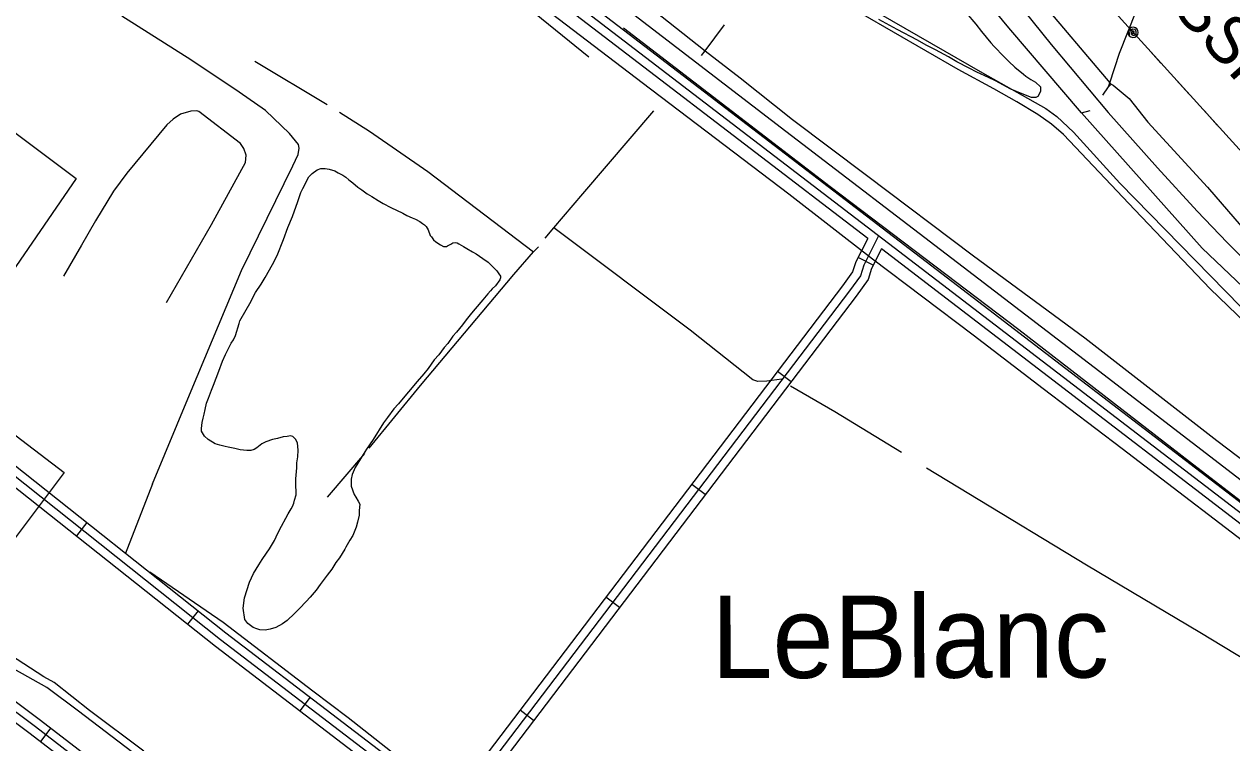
# Model space of a CAD drawing. Extents: x 3324104 to 3361979, y 612876 to 638273.
# Drawn here: x 3355626 to 3357754, y 632230 to 633497 of the extents above; entities that cross this region are included whole.
import ezdxf

# ---------------------------------------------------------------- set-up
doc = ezdxf.new("R2010")
doc.units = 0
for name, color, linetype in [('V-RAIL-IDEN', 7, 'Continuous'), ('V-RAIL-TRAK', 7, 'Continuous'), ('V-ROAD-CNTR', 7, 'Continuous'), ('V-SITE-OTLN', 7, 'Continuous'), ('V-SITE-VEGE', 7, 'Continuous'), ('V-TOPO-GNAM-IDEN', 7, 'Continuous'), ('V-TOPO-SHOR', 7, 'Continuous'), ('V-UTIL-LINE', 7, 'Continuous')]:
    doc.layers.add(name, color=color, linetype=linetype)

msp = doc.modelspace()

# ---------------------------------------------------------------- linework, layer by layer
at = {"layer": 'V-RAIL-TRAK'}
msp.add_line((3355679, 632336.4), (3355660.4, 632346.6), dxfattribs=at)
for points in [[(3356215.6, 635761.2), (3356284.7, 635591.1), (3356397, 635315.7), (3356492.2, 635083.5), (3356560, 634919.7), (3356618.9, 634783), (3356687.5, 634633.1), (3356729.4, 634548), (3356813.2, 634386.8), (3356880.5, 634264.7), (3356940.4, 634162), (3356992, 634077.6), (3357074.6, 633949.1), (3357125.6, 633873), (3357175.2, 633801), (3357225.5, 633732.6), (3357325.5, 633598.4), (3357435.2, 633461.4), (3357535.9, 633341.2), (3357622.9, 633243.9), (3357692.7, 633167.7), (3357745.2, 633112.4), (3357828.1, 633029.8)], [(3355803.7, 634092.1), (3356006.4, 633937.2), (3356202.2, 633787.1), (3356331, 633688.9), (3356519.9, 633543.8), (3356715, 633394.4), (3356973.1, 633198), (3357120.5, 633083.7)], [(3355660.4, 632346.6), (3355497.5, 632452.3), (3355389.9, 632538.5), (3355338.1, 632579), (3355081.1, 632775.2), (3354838.1, 632959.9), (3354736.5, 633039.5), (3354665.7, 633092.7)], [(3357120.5, 633083.7), (3357298, 632949.6), (3357421.2, 632854.9), (3357560.3, 632749), (3357832.3, 632540.7), (3358017.7, 632399.1), (3358165.1, 632285.5)], [(3356244.8, 631902.7), (3356234.1, 631908.9), (3356189.6, 631934.7), (3356156, 631953.1), (3356118.6, 631981.2), (3356060.8, 632025.8), (3355972.7, 632092.7), (3355862.4, 632178.6), (3355721.6, 632286), (3355665.9, 632327.4), (3355608.6, 632360), (3355536.8, 632401.4), (3355482, 632434.7), (3355447.1, 632458)], [(3355836.9, 632215.1), (3355741.3, 632287), (3355679, 632336.4)]]:
    msp.add_lwpolyline(points, dxfattribs=at)
at = {"layer": 'V-ROAD-CNTR'}
for p, q in [((3357122, 633072.4), (3357095.3, 633086)), ((3356977.2, 632866.7), (3356953.3, 632884.8)), ((3356826, 632667.6), (3356802.1, 632685.7)), ((3355736.7, 632618.4), (3355718.1, 632594.9)), ((3356674.8, 632468.5), (3356650.9, 632486.6)), ((3355932.5, 632463), (3355913.9, 632439.5)), ((3356130.1, 632310.3), (3356111.9, 632286.4)), ((3356523.6, 632269.4), (3356499.8, 632287.5)), ((3355673, 632256.3), (3355654.7, 632232.5))]:
    msp.add_line(p, q, dxfattribs=at)
for points in [[(3358019.6, 632437.2), (3357976, 632476), (3357233.8, 633045.3), (3356292.3, 633766.7), (3355060.3, 634700.7), (3354190.2, 635372.4), (3353533, 635873.8), (3353385.4, 635986.9)], [(3357973.3, 632497), (3357242.9, 633057.2), (3356301.4, 633778.6), (3355809.2, 634151.8)], [(3357112.4, 633119.4), (3356283.2, 633754.7), (3355799.1, 634121.8)], [(3356667, 633540.2), (3356968.1, 633308.6), (3357270.4, 633077.1), (3357511.3, 632892.6), (3357769.9, 632693)], [(3354440.4, 633195.5), (3354595.2, 633073.3), (3354743.7, 632957.5), (3354931.2, 632814.7), (3355122, 632677.9), (3355384.5, 632472.3), (3355654.9, 632270.2), (3355853.8, 632116.7), (3356020.3, 631989.3), (3356157.5, 631898.2), (3356178.3, 631895.5), (3356203.4, 631905.3), (3356249.5, 631948.5), (3356354.1, 632101)], [(3354421.8, 633171.9), (3354576.7, 633049.7), (3354725.4, 632933.7), (3354913.4, 632790.6), (3355104, 632653.9), (3355366.2, 632448.4), (3355636.8, 632246.3), (3355835.5, 632092.9), (3356002.9, 631964.8), (3356146.7, 631869.4), (3356182.1, 631864.8), (3356219.7, 631879.4), (3356272.4, 631928.8), (3356377.9, 632082.7)], [(3356374.5, 632104.3), (3356260.9, 631938.6), (3356211.5, 631892.3), (3356180.2, 631880.2), (3356152.1, 631883.8), (3356011.6, 631977.1), (3355844.7, 632104.8), (3355645.9, 632258.3), (3355375.4, 632460.4), (3355113, 632665.9), (3354922.3, 632802.6), (3354734.5, 632945.6), (3354586, 633061.5), (3354431.1, 633183.7)], [(3357131.4, 633123.7), (3357105.2, 633072.4), (3357099.2, 633053.5), (3357079.8, 633026.7), (3356384.2, 632110.6)], [(3357112.4, 633119.4), (3357091.3, 633078.1), (3357085.6, 633060.4), (3357067.8, 633035.6), (3356374.8, 632122.9)], [(3357136.6, 633100.9), (3357119.1, 633066.6), (3357112.7, 633046.7), (3357091.9, 633017.8), (3356398.6, 632104.7)], [(3358009.6, 632426), (3357966.4, 632464.5), (3357224.6, 633033.4), (3357136.6, 633100.9)], [(3355577.8, 633036.6), (3355588.3, 633022), (3355593.1, 633012.6), (3355592.9, 632993.3), (3355581.9, 632970.1), (3355539.7, 632906.8), (3355517.9, 632876.8), (3355513.2, 632836.4), (3355520.2, 632806.1), (3355531.4, 632780.9), (3355544.4, 632758.3), (3355575.1, 632727.6), (3355972.1, 632412.3), (3356882.6, 631715.2), (3357344.5, 631367.3), (3357364.6, 631354.1), (3357376.9, 631347.5), (3357393.1, 631340.4), (3357408.3, 631337.4), (3357420.1, 631337.3), (3357629.2, 631337.4), (3357692.6, 631341.9), (3357746, 631347.5), (3357788, 631350.2)], [(3355590, 633045.4), (3355601.2, 633029.8), (3355608.2, 633016.1), (3355607.9, 632989.9), (3355595, 632962.7), (3355552, 632898.2), (3355532.3, 632871.2), (3355528.4, 632837.2), (3355534.5, 632810.8), (3355544.7, 632787.8), (3355556.4, 632767.5), (3355585.1, 632738.8), (3355981.3, 632424.2), (3356374.8, 632122.9)], [(3355565.6, 633027.9), (3355575.5, 633014.2), (3355578.1, 633009), (3355577.9, 632996.8), (3355568.8, 632977.5), (3355527.3, 632915.3), (3355503.4, 632882.4), (3355498, 632835.6), (3355505.9, 632801.3), (3355518, 632774.1), (3355532.4, 632749.1), (3355565.1, 632716.3), (3355962.9, 632400.5), (3356354.1, 632101)]]:
    msp.add_lwpolyline(points, dxfattribs=at)
at = {"layer": 'V-SITE-OTLN'}
for points in [[(3355383.1, 633476), (3355717.7, 633225.3), (3355590.8, 633040)], [(3355524.4, 632837.6), (3355696.7, 632706.6), (3355535.7, 632492.5)]]:
    msp.add_lwpolyline(points, dxfattribs=at)
at = {"layer": 'V-SITE-VEGE'}
for points in [[(3357285.6, 633517.2), (3357302.6, 633497), (3357312.8, 633484.5), (3357329.2, 633464.2), (3357334.9, 633458), (3357351.8, 633440.3), (3357360.6, 633431.5), (3357371.4, 633421.1), (3357386.8, 633409.1), (3357390.9, 633405.4), (3357399.7, 633399.7), (3357407.9, 633395), (3357416.6, 633386.6), (3357416.6, 633378.4), (3357411.9, 633369.6), (3357408.2, 633367.6), (3357401, 633368.1), (3357387.1, 633372.9), (3357374.2, 633378.6), (3357364.4, 633382.8), (3357337.6, 633397), (3357325.2, 633403.3), (3357304.6, 633412.7), (3357291.2, 633419.5), (3357269.1, 633431), (3357254.6, 633439.4), (3357231.5, 633451.9), (3357215, 633460.3), (3357200, 633469.2), (3357164, 633488), (3357131.5, 633505.3)], [(3356005.8, 632974.3), (3356025.7, 633008.9), (3356029.3, 633016.6), (3356033.5, 633024.3), (3356043.4, 633038.7), (3356050.7, 633050.6), (3356063.3, 633073.2), (3356071.7, 633089.2), (3356083.2, 633117.6), (3356090.6, 633138.7), (3356098.5, 633157.8), (3356108, 633184.6), (3356113.7, 633200.6), (3356116.9, 633207.3), (3356127.4, 633227.9), (3356133.6, 633234.1), (3356142.4, 633240.2), (3356148.6, 633242.8), (3356156.4, 633242.7), (3356163.6, 633241.6), (3356173.4, 633238.5), (3356179.1, 633235.3), (3356187.3, 633231.1), (3356192.5, 633227.5), (3356198.1, 633222.8), (3356204.8, 633217.6), (3356214.1, 633209.8), (3356220.8, 633205.1), (3356230.6, 633197.8), (3356238.3, 633193.6), (3356249.6, 633186.3), (3356258.4, 633181.1), (3356272.3, 633173.7), (3356292.9, 633163.8), (3356300.1, 633160.1), (3356309.4, 633155.9), (3356315.6, 633153.3), (3356323.3, 633149.1), (3356327.9, 633146), (3356331.5, 633143.4), (3356334.1, 633140.3), (3356337.7, 633134.6), (3356341.2, 633124.7), (3356343.8, 633122.1), (3356347.4, 633116.9), (3356351.5, 633113.3), (3356359.7, 633108), (3356364.9, 633105.4), (3356370.1, 633105.4), (3356372.1, 633106.4), (3356377.8, 633109), (3356381.5, 633111.5), (3356386.1, 633112), (3356388.7, 633111.5), (3356391.8, 633109.9), (3356400, 633105.2), (3356405.7, 633101.5), (3356416, 633095.8), (3356422.2, 633092.1), (3356434, 633083.8), (3356443.3, 633077.5), (3356450, 633071.3), (3356458.7, 633062.4), (3356462.3, 633056.7), (3356465.4, 633052.6), (3356465.3, 633050), (3356463.8, 633046.4), (3356456.5, 633036.1), (3356450.7, 633030.4), (3356447.6, 633026.8), (3356442.9, 633021.7), (3356434.1, 633010.9), (3356420.5, 632995.5), (3356414.3, 632987.8), (3356404.9, 632975.9), (3356398.1, 632967.2), (3356387.7, 632954.3), (3356381.5, 632947.1), (3356372.6, 632934.3), (3356365.8, 632927.1), (3356356.4, 632914.2), (3356348.6, 632905.5), (3356337.7, 632890), (3356330.4, 632880.8), (3356318.4, 632866.9), (3356303.3, 632848.9), (3356296.5, 632841.2), (3356285.6, 632827.8), (3356277.2, 632819.1), (3356266.3, 632803.6), (3356259, 632794.4), (3356240.7, 632765), (3356229.2, 632748), (3356223, 632738.3), (3356209.4, 632715.6), (3356203.6, 632703.2)], [(3356203.6, 632703.2), (3356202, 632695), (3356201.9, 632682.6), (3356207.5, 632668.1), (3356210.6, 632663.4), (3356214.7, 632656.1), (3356217.2, 632650.9), (3356216.1, 632639.6), (3356216.1, 632631.3), (3356213.4, 632618.9), (3356210.8, 632610.1), (3356205, 632595.7), (3356199.8, 632587.5), (3356193, 632575.1), (3356190.9, 632571.5), (3356181.5, 632556), (3356175.2, 632547.8), (3356167.9, 632536.5), (3356160.1, 632525.7), (3356147.6, 632509.2), (3356140.3, 632499.4), (3356129.9, 632487.1), (3356123.1, 632479.4), (3356111.1, 632467.1), (3356102.3, 632458.3), (3356089.3, 632446), (3356081, 632439.8), (3356069.5, 632433.2), (3356059.7, 632430.7), (3356050.4, 632428.7), (3356041.1, 632429.2), (3356035.9, 632430.8), (3356029.2, 632433.5), (3356020, 632440.2), (3356014.8, 632447.5), (3356011.9, 632467.7), (3356014, 632485.8), (3356023, 632513.6), (3356029.8, 632528.6), (3356039.2, 632544), (3356045.5, 632553.3), (3356052.8, 632564.6), (3356058.5, 632572.3), (3356066.9, 632586.8), (3356073.2, 632599.6), (3356079.5, 632612), (3356087.3, 632626.4), (3356091, 632633.6), (3356096.2, 632642.4), (3356098.8, 632646.5), (3356100.9, 632652.7), (3356102.5, 632657.9), (3356105.2, 632667.2), (3356105.2, 632673.9), (3356104.7, 632682.7), (3356104.8, 632695.6), (3356106.5, 632715.2), (3356106.6, 632724), (3356108.2, 632734.3), (3356108.8, 632746.2), (3356107.3, 632759.2), (3356104.2, 632765.4), (3356099.6, 632770.1), (3356095, 632771.1), (3356089.3, 632770.1), (3356082.6, 632769.7), (3356072.2, 632766.6), (3356063.4, 632764.6), (3356052, 632760.5), (3356044.7, 632757), (3356035.9, 632750.3), (3356031.2, 632747.2), (3356025.5, 632745.2), (3356018.3, 632745.3), (3356006.4, 632746.9), (3355997.1, 632749), (3355985.2, 632751.2), (3355980.1, 632752.7), (3355970.8, 632754.9), (3355962.5, 632757.5), (3355950.2, 632764.8), (3355943.5, 632770.5), (3355938.4, 632779.4), (3355938.4, 632784.5), (3355939.5, 632794.9), (3355941.1, 632802.6), (3355943.2, 632809.8), (3355944.8, 632817.6), (3355947.5, 632828.9), (3355950.6, 632837.7), (3355955.9, 632851.6), (3355959.6, 632860.4), (3355969, 632885.1), (3355975.4, 632902.7), (3355980.6, 632914.5), (3355986.9, 632927.4), (3355990.6, 632934.6), (3355994.7, 632940.8), (3355998.4, 632948), (3356004.7, 632969.2), (3356005.8, 632974.3)]]:
    msp.add_lwpolyline(points, dxfattribs=at)
at = {"layer": 'V-TOPO-SHOR'}
for p, q in [((3357410.9, 633545), (3357538.8, 633394)), ((3356819.3, 633441.8), (3356825.7, 633450.1)), ((3356032.3, 633432.2), (3356159.9, 633355.6)), ((3357538.8, 633394), (3357541.2, 633391.2)), ((3356160.3, 632663.3), (3356226.2, 632740.1)), ((3355852.2, 632686.8), (3355803.7, 632562.8))]:
    msp.add_line(p, q, dxfattribs=at)
for points in [[(3357488.8, 633340.8), (3357361, 633490.5), (3357247.1, 633629.7), (3357185, 633714.3), (3357084.4, 633863.2), (3357001, 633991), (3356930, 634103.5), (3356845.4, 634250.9), (3356752.5, 634412.9), (3356676.9, 634563), (3356602.8, 634721.4), (3356559.6, 634821.2), (3356583.3, 634831.5)], [(3357538.8, 633394), (3357555.5, 633446.2), (3357600.1, 633557.9), (3357668.1, 633743.9), (3357760.7, 633976.4), (3357840.6, 634175.6), (3357880.2, 634274.2), (3357940.3, 634417.8)], [(3356621, 633438.9), (3356490.9, 633544.8), (3356236.1, 633735)], [(3356766.2, 633621.7), (3356740.9, 633586.4), (3356722.7, 633554.5), (3356720.5, 633542.6), (3356722.5, 633535), (3356735.7, 633521), (3356825.7, 633450.1), (3356860, 633495.8)], [(3357087.8, 633542.4), (3357314.5, 633411.6), (3357426.1, 633348.2), (3357445.5, 633334.2), (3357474.5, 633306.9), (3357556.1, 633216.6), (3357822.2, 632944.9)], [(3355852.2, 632686.8), (3355917.2, 632843.6), (3356009.1, 633062.9), (3356099.3, 633247.4), (3356108.5, 633267.5), (3356110.7, 633278.7), (3356109.3, 633284.9), (3356093.4, 633304.5), (3356051.3, 633345.1), (3356004.8, 633377.4), (3355919.6, 633434.4), (3355798.3, 633511)], [(3357841.5, 632908.6), (3357715.6, 633030.5), (3357582.9, 633169.8), (3357457.1, 633302.8), (3357435.7, 633321), (3357412.1, 633337.9), (3357374.7, 633360.4), (3357334.5, 633382.9), (3357271.4, 633417.4), (3357100.8, 633515.9)], [(3357948.4, 632536.3), (3357936.6, 632535), (3357928.2, 632535.1), (3357910.9, 632547), (3357679, 632725.2), (3357378.5, 632958.1), (3357046.1, 633210.1), (3356681.9, 633490)], [(3356825.7, 633450.1), (3356887.3, 633402.4), (3356979.4, 633328.8), (3357110.2, 633231.2), (3357298.6, 633088.8), (3357494.6, 632944.2), (3357727.2, 632763.2), (3357885.1, 632643.2), (3357976.5, 632575.8)], [(3357526.5, 633371.9), (3357536.4, 633386.4), (3357538.8, 633394)], [(3357536.4, 633386.4), (3357541.2, 633391.2), (3357541.3, 633391.3), (3357544.7, 633389.9), (3357573.1, 633366), (3357605.5, 633324.1), (3357710.6, 633210), (3357770, 633141), (3357814.9, 633088.9)], [(3355876.5, 633006.7), (3355956, 633144), (3356015.9, 633253.5), (3356017.4, 633266), (3356013.3, 633277.9), (3356007, 633287), (3355933.6, 633343.1), (3355930.2, 633344.5), (3355919.7, 633343.9), (3355901.6, 633338.4), (3355888.3, 633329.5), (3355877.1, 633319.8), (3355807, 633234.7)], [(3356181.4, 633342.2), (3356234.7, 633308.5), (3356337.2, 633237.6), (3356523.5, 633095.8), (3356531.9, 633104.8)], [(3356543.8, 633120), (3356559.4, 633138.3), (3356610.4, 633198.2), (3356735.2, 633344.2)], [(3358092.3, 632734.4), (3357967.1, 632849.3), (3357701.5, 633102.2), (3357488.8, 633340.8), (3357504.1, 633344.9)], [(3355807, 633234.7), (3355783.3, 633202.9), (3355751.7, 633150.5), (3355727.2, 633107.3), (3355695.5, 633052.8)], [(3356961.1, 632871), (3356934.7, 632867.7), (3356918.6, 632867.1), (3356909.6, 632870), (3356799.6, 632957.7), (3356559.4, 633138.3)], [(3356233.9, 632749.8), (3356324.4, 632859.8), (3356488.5, 633055.7), (3356523.5, 633095.8)], [(3357171.8, 632741.7), (3357054, 632813.4), (3356976.4, 632859.1)], [(3357928, 632284.6), (3357697.2, 632424.5), (3357497.6, 632543.4), (3357290.3, 632669.2), (3357215.5, 632714.3)], [(3355847.7, 632531.7), (3355976.6, 632442.5), (3356134.5, 632321.8), (3356196.8, 632274.8)], [(3356196.8, 632274.8), (3356321.5, 632176.4), (3356383, 632128.3)]]:
    msp.add_lwpolyline(points, dxfattribs=at)
at = {"layer": 'V-UTIL-LINE'}
for points in [[(3359778.1, 631804.5), (3358880.1, 632347.8), (3358382, 632698.4), (3357961.3, 633061.4), (3357548.2, 633517.7), (3357255.4, 633931.7), (3356960.8, 634342.1), (3356736.1, 634811.3), (3356526.7, 635349.8), (3356308.1, 635878.7), (3356075.3, 636434.9), (3356085, 636489.4)], [(3357579.8, 633482.8), (3357579.2, 633480), (3357581.3, 633480.9), (3357581.9, 633483.5), (3357579.7, 633485.5), (3357577.1, 633483.3), (3357576.7, 633478.7), (3357580.6, 633477), (3357585, 633479.2), (3357585.4, 633483.7), (3357583.2, 633487.6), (3357578.4, 633488.3), (3357574.2, 633484.8), (3357573.1, 633476.8), (3357576, 633474.7), (3357579.4, 633473.8), (3357582.8, 633474.3), (3357585.9, 633476.1), (3357587.9, 633478.9), (3357588.8, 633482.3), (3357588.3, 633485.8), (3357586.5, 633488.8), (3357583.7, 633490.9), (3357580.3, 633491.8), (3357576.8, 633491.3), (3357573.8, 633489.5), (3357571.7, 633486.6), (3357570.8, 633483.2), (3357571.3, 633479.8), (3357573.1, 633476.8)], [(3357628.8, 633428.7), (3357606, 633453.9)], [(3357678.5, 633373.8), (3357655.6, 633399)], [(3357728.1, 633319), (3357705.3, 633344.2)]]:
    msp.add_lwpolyline(points, dxfattribs=at)

# ---------------------------------------------------------------- texts
at = {"layer": 'V-RAIL-IDEN'}
msp.add_text('MISSISSIPPI', height=83, rotation=311.5765, dxfattribs=at).set_placement((3357445.1, 633751.4))
at = {"layer": 'V-TOPO-GNAM-IDEN'}
msp.add_text('LeBlanc', height=145, rotation=0.0909, dxfattribs=at).set_placement((3356836.6, 632344.2))

doc.saveas('drawing.dxf')
